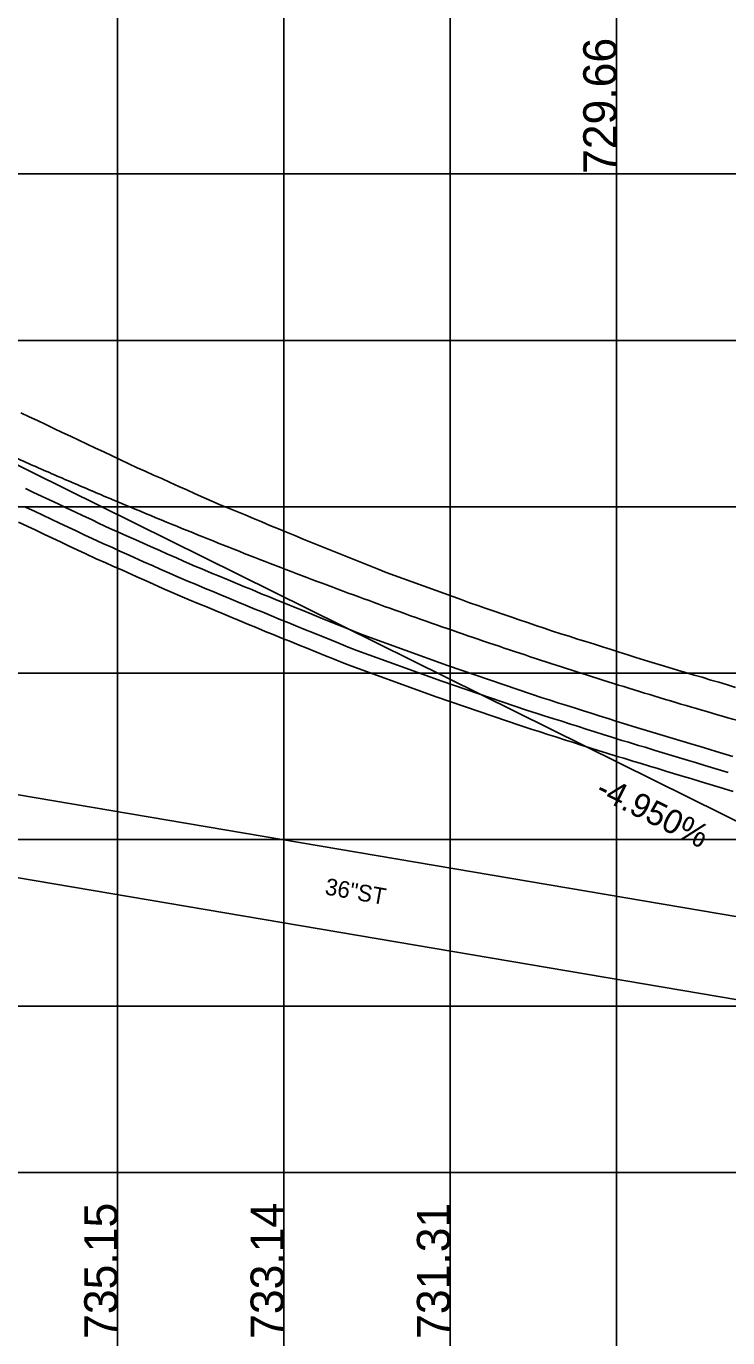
# Model space of a CAD drawing. Extents: x -7164 to 2214450, y -19642 to 253469.
# Drawn here: x 3572.6 to 3783.4, y -2399.7 to -2005.6 of the extents above; entities that cross this region are included whole.
import ezdxf

# ---------------------------------------------------------------- set-up
doc = ezdxf.new("R2010")
doc.units = 0
for name, color, linetype in [('DESIGN - PROFILE - Proposed', 7, 'Continuous'), ('DESIGN - PROFILE - Proposed Text', 7, 'Continuous'), ('DESIGN - SHEET - Light Grid', 7, 'Continuous'), ('SURVEY - PROFILE - Drainage - Storm Sewer', 7, 'Continuous'), ('SURVEY - PROFILE - Drainage - Storm Sewer Text', 7, 'Continuous'), ('SURVEY - PROFILE - Ground Line with Text', 7, 'Continuous'), ('SURVEY - PROFILE - Utilities - Cable with Text', 7, 'Continuous'), ('SURVEY - PROFILE - Utilities - Electric with Text', 7, 'Continuous'), ('XTREE', 7, 'Continuous')]:
    doc.layers.add(name, color=color, linetype=linetype)

msp = doc.modelspace()

# ---------------------------------------------------------------- linework, layer by layer
at = {"layer": 'DESIGN - PROFILE - Proposed'}
msp.add_spline([(3497.5, -2101.57), (3510, -2107.7), (3522.5, -2113.72), (3535, -2119.62), (3547.5, -2125.41), (3560, -2131.09), (3572.5, -2136.65), (3585, -2142.1), (3597.5, -2147.43), (3610, -2152.65), (3622.5, -2157.76), (3635, -2162.75), (3647.5, -2167.63), (3660, -2172.4), (3672.5, -2177.05), (3685, -2181.59), (3697.5, -2186.01), (3710, -2190.32), (3722.5, -2194.52), (3735, -2198.6), (3747.5, -2202.57), (3760, -2206.43), (3772.5, -2210.17), (3785, -2213.8), (3797.5, -2217.31), (3810, -2220.71), (3822.5, -2224), (3835, -2227.17), (3847.5, -2230.23), (3860, -2233.18), (3872.5, -2236.01), (3885, -2238.73), (3897.5, -2241.33), (3910, -2243.82), (3922.5, -2246.2), (3935, -2248.46), (3947.5, -2250.61), (3960, -2252.65), (3972.5, -2254.57), (3985, -2256.38), (3997.5, -2258.07), (4010, -2259.65), (4022.5, -2261.12), (4035, -2262.47), (4047.5, -2263.71), (4060, -2264.84), (4072.5, -2265.85), (4085, -2266.75), (4097.5, -2267.53), (4110, -2268.2), (4122.5, -2268.76)], degree=3, dxfattribs=at)
msp.add_spline([(3497.5, -2101.57), (3510, -2107.7), (3522.5, -2113.72), (3535, -2119.62), (3547.5, -2125.41), (3560, -2131.09), (3572.5, -2136.65), (3585, -2142.1), (3597.5, -2147.43), (3610, -2152.65), (3622.5, -2157.76), (3635, -2162.75), (3647.5, -2167.63), (3660, -2172.4), (3672.5, -2177.05), (3685, -2181.59), (3697.5, -2186.01), (3710, -2190.32), (3722.5, -2194.52), (3735, -2198.6), (3747.5, -2202.57), (3760, -2206.43), (3772.5, -2210.17), (3785, -2213.8), (3797.5, -2217.31), (3810, -2220.71), (3822.5, -2224), (3835, -2227.17), (3847.5, -2230.23), (3860, -2233.18), (3872.5, -2236.01), (3885, -2238.73), (3897.5, -2241.33), (3910, -2243.82), (3922.5, -2246.2), (3935, -2248.46), (3947.5, -2250.61), (3960, -2252.65), (3972.5, -2254.57), (3985, -2256.38), (3997.5, -2258.07), (4010, -2259.65), (4022.5, -2261.12), (4035, -2262.47), (4047.5, -2263.71), (4060, -2264.84), (4072.5, -2265.85), (4085, -2266.75), (4097.5, -2267.53), (4110, -2268.2), (4122.5, -2268.76)], degree=3, dxfattribs=at)
at = {"layer": 'DESIGN - PROFILE - Proposed Text'}
msp.add_line((3497.5, -2101.57), (3804.62, -2253.6), dxfattribs=at)
msp.add_line((3497.5, -2101.57), (3804.62, -2253.6), dxfattribs=at)
at = {"layer": 'DESIGN - SHEET - Light Grid'}
for p, q in [((3600, -3000), (3600, -1000)), ((3600, -3000), (3600, -1000)), ((3650, -3000), (3650, -1000)), ((3650, -3000), (3650, -1000)), ((3700, -3000), (3700, -1000)), ((3700, -3000), (3700, -1000)), ((3750, -3000), (3750, -1000)), ((3750, -3000), (3750, -1000)), ((0, -2050), (12400, -2050)), ((0, -2050), (12400, -2050)), ((0, -2100), (12400, -2100)), ((0, -2100), (12400, -2100)), ((0, -2150), (12400, -2150)), ((0, -2150), (12400, -2150)), ((0, -2200), (12400, -2200)), ((0, -2200), (12400, -2200)), ((0, -2250), (12400, -2250)), ((0, -2250), (12400, -2250)), ((0, -2300), (12400, -2300)), ((0, -2300), (12400, -2300)), ((0, -2350), (12400, -2350)), ((0, -2350), (12400, -2350))]:
    msp.add_line(p, q, dxfattribs=at)
at = {"layer": 'SURVEY - PROFILE - Drainage - Storm Sewer'}
for p, q in [((3948.81, -2300.7), (3367.97, -2202.2)), ((3948.81, -2300.7), (3367.97, -2202.2)), ((3948.81, -2325.7), (3367.97, -2227.2)), ((3948.81, -2325.7), (3367.97, -2227.2))]:
    msp.add_line(p, q, dxfattribs=at)
at = {"layer": 'SURVEY - PROFILE - Ground Line with Text'}
for points in [[(3570.92, -2121.78), (3573.42, -2122.95), (3575.91, -2124.11), (3578.42, -2125.29), (3580.9, -2126.45), (3583.42, -2127.65), (3585.9, -2128.81), (3588.42, -2130.01), (3590.89, -2131.16), (3593.43, -2132.37), (3595.89, -2133.52), (3598.43, -2134.73), (3600.88, -2135.88), (3603.44, -2137.09), (3605.88, -2138.24), (3608.32, -2139.29), (3610.87, -2140.47), (3613.32, -2141.52), (3615.87, -2142.7), (3618.4, -2143.87), (3620.86, -2144.93), (3623.38, -2146.1), (3625.86, -2147.16), (3628.37, -2148.32), (3630.85, -2149.39), (3633.36, -2150.38), (3635.85, -2151.45), (3638.36, -2152.44), (3640.84, -2153.51), (3643.35, -2154.51), (3645.84, -2155.57), (3648.35, -2156.57), (3650.83, -2157.63), (3653.35, -2158.63), (3655.83, -2159.7), (3658.34, -2160.69), (3660.82, -2161.7), (3663.33, -2162.69), (3665.82, -2163.71), (3668.32, -2164.7), (3670.82, -2165.72), (3673.32, -2166.74), (3675.81, -2167.73), (3678.32, -2168.75), (3680.81, -2169.74), (3683.3, -2170.64), (3685.8, -2171.55), (3688.29, -2172.45), (3690.8, -2173.36), (3693.28, -2174.26)], [(3570.92, -2121.78), (3573.42, -2122.95), (3575.91, -2124.11), (3578.42, -2125.29), (3580.9, -2126.45), (3583.42, -2127.65), (3585.9, -2128.81), (3588.42, -2130.01), (3590.89, -2131.16), (3593.43, -2132.37), (3595.89, -2133.52), (3598.43, -2134.73), (3600.88, -2135.88), (3603.44, -2137.09), (3605.88, -2138.24), (3608.32, -2139.29), (3610.87, -2140.47), (3613.32, -2141.52), (3615.87, -2142.7), (3618.4, -2143.87), (3620.86, -2144.93), (3623.38, -2146.1), (3625.86, -2147.16), (3628.37, -2148.32), (3630.85, -2149.39), (3633.36, -2150.38), (3635.85, -2151.45), (3638.36, -2152.44), (3640.84, -2153.51), (3643.35, -2154.51), (3645.84, -2155.57), (3648.35, -2156.57), (3650.83, -2157.63), (3653.35, -2158.63), (3655.83, -2159.7), (3658.34, -2160.69), (3660.82, -2161.7), (3663.33, -2162.69), (3665.82, -2163.71), (3668.32, -2164.7), (3670.82, -2165.72), (3673.32, -2166.74), (3675.81, -2167.73), (3678.32, -2168.75), (3680.81, -2169.74), (3683.3, -2170.64), (3685.8, -2171.55), (3688.29, -2172.45), (3690.8, -2173.36), (3693.28, -2174.26)], [(3693.28, -2174.26), (3695.8, -2175.18), (3698.28, -2176.08), (3700.79, -2176.99), (3703.27, -2177.89), (3705.79, -2178.81), (3708.27, -2179.65), (3710.79, -2180.51), (3713.27, -2181.36), (3715.79, -2182.21), (3718.27, -2183.06), (3720.78, -2183.92), (3723.28, -2184.77), (3725.78, -2185.62), (3728.28, -2186.47), (3730.78, -2187.33), (3733.29, -2188.14), (3735.78, -2188.9), (3738.32, -2189.72), (3740.77, -2190.49), (3743.34, -2191.31), (3745.77, -2192.07), (3748.36, -2192.9), (3750.77, -2193.65), (3753.39, -2194.5), (3755.77, -2195.23), (3758.4, -2196.06), (3760.76, -2196.73), (3763.39, -2197.56), (3765.76, -2198.23), (3768.38, -2199.06), (3770.76, -2199.73), (3773.37, -2200.56), (3775.76, -2201.23), (3778.37, -2202.06), (3780.76, -2202.73), (3783.36, -2203.53), (3785.75, -2204.24)], [(3693.28, -2174.26), (3695.8, -2175.18), (3698.28, -2176.08), (3700.79, -2176.99), (3703.27, -2177.89), (3705.79, -2178.81), (3708.27, -2179.65), (3710.79, -2180.51), (3713.27, -2181.36), (3715.79, -2182.21), (3718.27, -2183.06), (3720.78, -2183.92), (3723.28, -2184.77), (3725.78, -2185.62), (3728.28, -2186.47), (3730.78, -2187.33), (3733.29, -2188.14), (3735.78, -2188.9), (3738.32, -2189.72), (3740.77, -2190.49), (3743.34, -2191.31), (3745.77, -2192.07), (3748.36, -2192.9), (3750.77, -2193.65), (3753.39, -2194.5), (3755.77, -2195.23), (3758.4, -2196.06), (3760.76, -2196.73), (3763.39, -2197.56), (3765.76, -2198.23), (3768.38, -2199.06), (3770.76, -2199.73), (3773.37, -2200.56), (3775.76, -2201.23), (3778.37, -2202.06), (3780.76, -2202.73), (3783.36, -2203.53), (3785.75, -2204.24)]]:
    msp.add_lwpolyline(points, dxfattribs=at)
at = {"layer": 'SURVEY - PROFILE - Utilities - Cable with Text'}
msp.add_lwpolyline([(3570.25, -2154.61), (3573.1, -2155.94), (3575.25, -2156.96), (3578.09, -2158.29), (3580.26, -2159.32), (3583.09, -2160.65), (3585.26, -2161.68), (3588.08, -2163), (3590.27, -2164.04), (3593.59, -2165.6), (3596.46, -2166.83), (3598.65, -2167.84), (3601.47, -2169.06), (3605.8, -2171.07), (3608.64, -2172.28), (3610.79, -2173.28), (3613.64, -2174.5), (3615.77, -2175.49), (3619.42, -2177.06), (3621.55, -2177.9), (3624.41, -2179.13), (3626.54, -2179.97), (3629.41, -2181.2), (3631.54, -2182.05), (3634.4, -2183.28), (3636.54, -2184.12), (3639.4, -2185.35), (3641.53, -2186.2), (3644.39, -2187.43), (3646.78, -2188.37), (3649.64, -2189.54), (3651.77, -2190.38), (3654.64, -2191.55), (3656.76, -2192.39), (3662.51, -2194.74), (3664.63, -2195.58), (3667.52, -2196.76), (3670.18, -2197.81), (3695.84, -2207.13), (3721.33, -2215.82), (3724.65, -2216.89), (3726.74, -2217.54), (3729.67, -2218.48), (3731.73, -2219.12), (3734.7, -2220.08), (3736.73, -2220.71), (3739.72, -2221.67), (3741.72, -2222.3), (3744.74, -2223.27), (3746.81, -2223.91), (3750.19, -2224.98), (3752.17, -2225.54), (3755.19, -2226.5), (3757.16, -2227.05), (3760.18, -2228.01), (3762.16, -2228.57), (3765.17, -2229.52), (3767.16, -2230.08), (3770.17, -2231.03), (3772.3, -2231.64), (3775.13, -2232.5), (3777.12, -2233.09), (3780.12, -2234), (3782.12, -2234.6), (3785.11, -2235.51)], dxfattribs=at)
msp.add_lwpolyline([(3570.25, -2154.61), (3573.1, -2155.94), (3575.25, -2156.96), (3578.09, -2158.29), (3580.26, -2159.32), (3583.09, -2160.65), (3585.26, -2161.68), (3588.08, -2163), (3590.27, -2164.04), (3593.59, -2165.6), (3596.46, -2166.83), (3598.65, -2167.84), (3601.47, -2169.06), (3605.8, -2171.07), (3608.64, -2172.28), (3610.79, -2173.28), (3613.64, -2174.5), (3615.77, -2175.49), (3619.42, -2177.06), (3621.55, -2177.9), (3624.41, -2179.13), (3626.54, -2179.97), (3629.41, -2181.2), (3631.54, -2182.05), (3634.4, -2183.28), (3636.54, -2184.12), (3639.4, -2185.35), (3641.53, -2186.2), (3644.39, -2187.43), (3646.78, -2188.37), (3649.64, -2189.54), (3651.77, -2190.38), (3654.64, -2191.55), (3656.76, -2192.39), (3662.51, -2194.74), (3664.63, -2195.58), (3667.52, -2196.76), (3670.18, -2197.81), (3695.84, -2207.13), (3721.33, -2215.82), (3724.65, -2216.89), (3726.74, -2217.54), (3729.67, -2218.48), (3731.73, -2219.12), (3734.7, -2220.08), (3736.73, -2220.71), (3739.72, -2221.67), (3741.72, -2222.3), (3744.74, -2223.27), (3746.81, -2223.91), (3750.19, -2224.98), (3752.17, -2225.54), (3755.19, -2226.5), (3757.16, -2227.05), (3760.18, -2228.01), (3762.16, -2228.57), (3765.17, -2229.52), (3767.16, -2230.08), (3770.17, -2231.03), (3772.3, -2231.64), (3775.13, -2232.5), (3777.12, -2233.09), (3780.12, -2234), (3782.12, -2234.6), (3785.11, -2235.51)], dxfattribs=at)
at = {"layer": 'SURVEY - PROFILE - Utilities - Electric with Text'}
for points in [[(3572.38, -2144.54), (3574.52, -2145.56), (3577.37, -2146.9), (3579.52, -2147.92), (3582.36, -2149.25), (3584.53, -2150.28), (3587.35, -2151.6), (3589.53, -2152.64), (3592.35, -2153.96), (3594.53, -2155), (3597.69, -2156.47), (3600.54, -2157.7), (3602.72, -2158.71), (3605.55, -2159.93), (3609.88, -2161.93), (3612.71, -2163.15), (3614.86, -2164.15), (3617.71, -2165.37), (3619.85, -2166.36), (3623.23, -2167.81), (3625.36, -2168.65), (3628.22, -2169.89), (3630.36, -2170.73), (3633.22, -2171.96), (3635.35, -2172.8), (3638.21, -2174.03), (3640.35, -2174.88), (3643.21, -2176.11), (3645.35, -2176.95), (3648.21, -2178.18), (3650.51, -2179.09), (3653.37, -2180.26), (3655.5, -2181.1), (3658.37, -2182.27), (3660.49, -2183.11), (3666.24, -2185.46), (3668.36, -2186.3), (3671.25, -2187.48), (3673.72, -2188.46), (3699.16, -2197.69), (3724.48, -2206.33), (3727.66, -2207.36), (3729.75, -2208), (3732.69, -2208.95), (3734.75, -2209.59), (3737.71, -2210.54), (3739.74, -2211.17), (3742.73, -2212.14), (3744.74, -2212.76), (3747.76, -2213.74), (3749.79, -2214.37), (3753.06, -2215.4), (3755.03, -2215.96), (3758.05, -2216.91), (3760.03, -2217.47), (3763.05, -2218.43), (3765.03, -2218.99), (3768.04, -2219.94), (3770.03, -2220.5), (3773.03, -2221.45), (3775.12, -2222.04), (3778.01, -2222.92), (3780, -2223.51), (3783, -2224.43), (3785, -2225.02)], [(3572.38, -2144.54), (3574.52, -2145.56), (3577.37, -2146.9), (3579.52, -2147.92), (3582.36, -2149.25), (3584.53, -2150.28), (3587.35, -2151.6), (3589.53, -2152.64), (3592.35, -2153.96), (3594.53, -2155), (3597.69, -2156.47), (3600.54, -2157.7), (3602.72, -2158.71), (3605.55, -2159.93), (3609.88, -2161.93), (3612.71, -2163.15), (3614.86, -2164.15), (3617.71, -2165.37), (3619.85, -2166.36), (3623.23, -2167.81), (3625.36, -2168.65), (3628.22, -2169.89), (3630.36, -2170.73), (3633.22, -2171.96), (3635.35, -2172.8), (3638.21, -2174.03), (3640.35, -2174.88), (3643.21, -2176.11), (3645.35, -2176.95), (3648.21, -2178.18), (3650.51, -2179.09), (3653.37, -2180.26), (3655.5, -2181.1), (3658.37, -2182.27), (3660.49, -2183.11), (3666.24, -2185.46), (3668.36, -2186.3), (3671.25, -2187.48), (3673.72, -2188.46), (3699.16, -2197.69), (3724.48, -2206.33), (3727.66, -2207.36), (3729.75, -2208), (3732.69, -2208.95), (3734.75, -2209.59), (3737.71, -2210.54), (3739.74, -2211.17), (3742.73, -2212.14), (3744.74, -2212.76), (3747.76, -2213.74), (3749.79, -2214.37), (3753.06, -2215.4), (3755.03, -2215.96), (3758.05, -2216.91), (3760.03, -2217.47), (3763.05, -2218.43), (3765.03, -2218.99), (3768.04, -2219.94), (3770.03, -2220.5), (3773.03, -2221.45), (3775.12, -2222.04), (3778.01, -2222.92), (3780, -2223.51), (3783, -2224.43), (3785, -2225.02)], [(3572.39, -2150.08), (3575.23, -2151.42), (3577.39, -2152.44), (3580.23, -2153.77), (3582.39, -2154.8), (3585.22, -2156.13), (3587.4, -2157.16), (3590.22, -2158.48), (3592.4, -2159.52), (3595.64, -2161.04), (3598.5, -2162.27), (3600.68, -2163.28), (3603.51, -2164.49), (3607.84, -2166.5), (3610.68, -2167.72), (3612.83, -2168.71), (3615.67, -2169.94), (3617.81, -2170.93), (3621.32, -2172.43), (3623.45, -2173.28), (3626.32, -2174.51), (3628.45, -2175.35), (3631.31, -2176.58), (3633.45, -2177.43), (3636.31, -2178.66), (3638.44, -2179.5), (3641.3, -2180.73), (3643.44, -2181.57), (3646.3, -2182.8), (3648.64, -2183.73), (3651.51, -2184.9), (3653.63, -2185.74), (3656.5, -2186.91), (3658.62, -2187.75), (3664.38, -2190.1), (3666.49, -2190.94), (3669.38, -2192.12), (3671.95, -2193.14), (3697.5, -2202.41), (3722.91, -2211.07), (3726.16, -2212.12), (3728.24, -2212.77), (3731.18, -2213.72), (3733.24, -2214.35), (3736.2, -2215.31), (3738.24, -2215.94), (3741.23, -2216.91), (3743.23, -2217.53), (3746.25, -2218.5), (3748.3, -2219.14), (3751.63, -2220.19), (3753.6, -2220.75), (3756.62, -2221.7), (3758.6, -2222.26), (3761.61, -2223.22), (3763.6, -2223.78), (3766.61, -2224.73), (3768.59, -2225.29), (3771.6, -2226.24), (3773.71, -2226.84), (3776.57, -2227.71), (3778.56, -2228.3), (3781.56, -2229.22), (3783.56, -2229.81)], [(3572.39, -2150.08), (3575.23, -2151.42), (3577.39, -2152.44), (3580.23, -2153.77), (3582.39, -2154.8), (3585.22, -2156.13), (3587.4, -2157.16), (3590.22, -2158.48), (3592.4, -2159.52), (3595.64, -2161.04), (3598.5, -2162.27), (3600.68, -2163.28), (3603.51, -2164.49), (3607.84, -2166.5), (3610.68, -2167.72), (3612.83, -2168.71), (3615.67, -2169.94), (3617.81, -2170.93), (3621.32, -2172.43), (3623.45, -2173.28), (3626.32, -2174.51), (3628.45, -2175.35), (3631.31, -2176.58), (3633.45, -2177.43), (3636.31, -2178.66), (3638.44, -2179.5), (3641.3, -2180.73), (3643.44, -2181.57), (3646.3, -2182.8), (3648.64, -2183.73), (3651.51, -2184.9), (3653.63, -2185.74), (3656.5, -2186.91), (3658.62, -2187.75), (3664.38, -2190.1), (3666.49, -2190.94), (3669.38, -2192.12), (3671.95, -2193.14), (3697.5, -2202.41), (3722.91, -2211.07), (3726.16, -2212.12), (3728.24, -2212.77), (3731.18, -2213.72), (3733.24, -2214.35), (3736.2, -2215.31), (3738.24, -2215.94), (3741.23, -2216.91), (3743.23, -2217.53), (3746.25, -2218.5), (3748.3, -2219.14), (3751.63, -2220.19), (3753.6, -2220.75), (3756.62, -2221.7), (3758.6, -2222.26), (3761.61, -2223.22), (3763.6, -2223.78), (3766.61, -2224.73), (3768.59, -2225.29), (3771.6, -2226.24), (3773.71, -2226.84), (3776.57, -2227.71), (3778.56, -2228.3), (3781.56, -2229.22), (3783.56, -2229.81)]]:
    msp.add_lwpolyline(points, dxfattribs=at)
at = {"layer": 'XTREE'}
msp.add_line((2273.46, -1495.67), (3810, -2256.26), dxfattribs=at)
msp.add_line((2273.46, -1495.67), (3810, -2256.26), dxfattribs=at)

# ---------------------------------------------------------------- texts
at = {"layer": 'DESIGN - PROFILE - Proposed Text'}
for s, height, rotation, p in [('729.66', 10, 90, (3750, -2050)), ('729.66', 10, 90, (3750, -2050)), ('-4.950%', 7.2, 333.6646, (3743.27, -2236.84)), ('-4.950%', 7.2, 333.6646, (3743.27, -2236.84)), ('735.15', 10, 90, (3600, -2400)), ('735.15', 10, 90, (3600, -2400)), ('733.14', 10, 90, (3650, -2400)), ('733.14', 10, 90, (3650, -2400)), ('731.31', 10, 90, (3700, -2400)), ('731.31', 10, 90, (3700, -2400))]:
    msp.add_text(s, height=height, rotation=rotation, dxfattribs=at).set_placement(p)
at = {"layer": 'SURVEY - PROFILE - Drainage - Storm Sewer Text'}
msp.add_text('36"ST', height=5, rotation=349.86, dxfattribs=at).set_placement((3662.12, -2266.41))
msp.add_text('36"ST', height=5, rotation=349.86, dxfattribs=at).set_placement((3662.12, -2266.41))

doc.saveas('drawing.dxf')
